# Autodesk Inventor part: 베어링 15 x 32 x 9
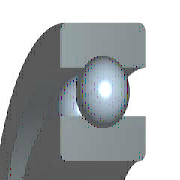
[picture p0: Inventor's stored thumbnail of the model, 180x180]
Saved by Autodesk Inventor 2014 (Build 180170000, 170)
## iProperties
IsCustomPart: 0
Created: 2012-02
Part Number: 베어링 15 x 32 x 9
Material: 강철, 연강
Description: 깊은 그루브 볼 베어링
Document SubType Name: Modeling
Standard: KS B 2023
Designer: mduedu
Standards Organization: KS
Language: ko-KR
Size Designation: 6002 - 15 x 32 x 9
Categories: <MemberInstance><Categories><Category DisplayName="샤프트 부품" InternalName="7f7aeb1f-a693-4053-b835-cee3144e0d98" Mnemonic="SHFT"><Category DisplayName="베어링" Inter
Density: 1 g/cm^3
Appearance: Yellow
Author: mduedu
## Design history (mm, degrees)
sketch "스케치" dims "d0" = 4.42 (= -0.26 x WD + 0.26 x BD)
  geometry: L1 (2.29, 11.75)-(6.71, 11.75); L2 (4.5, 11.75)-(4.5, 9.54); L3 (4.5, 11.75)-(4.5, 13.96); L4 (2.858, 10.271)-(0, 10.271); L5 (0, 7.5)-(9, 7.5); L6 (2.858, 13.229)-(0, 13.229); L7 (0, 16)-(9, 16); L8 (9, 7.5)-(9, 10.271); L9 (6.142, 10.271)-(9, 10.271); L10 (6.142, 13.229)-(9, 13.229); L11 (9, 16)-(9, 13.229); L12 (-1.4, 0)-(8.4, 0) reference; L13 (0, -0.3)-(0, 5.3) reference
  constraints: 22 end point, 4 point on line, 2 collinear, 2 perpendicular, 2 symmetric about line, 1 midpoint, 1 parallel, 14 other
  dimensions: "d9" = 15 diameter of L5 L12 (= WD); "d11" = 32 diameter of L7 L12 (= BD); "d12" = 9 distance between parallel lines of L8 L13 (= KB); "d13" = 20.542 diameter of L9 L12 (= 0.326 x BD + 0.674 x WD)
revolve "본체" stored, may be unused: angle "d6" = 90 deg
revolve "볼" stored, may be unused: angle "d7" = 90 deg
pattern_circular "IDS_ARRAYBALL[SIMPL:T]" dims angle "d3" = 360 deg
body "Solid1"
fillet "모깎기1" dims "d1" = 0.3 (= KRS)
other parameters: "WD" = 15 [user parameter; used in 5 equation terms], "BD" = 32 [user parameter; used in 5 equation terms], "KB" = 9 [user parameter; used in 1 equation term], "KRS" = 0.3 [user parameter; used in 1 equation term], "d4" = 0, "d5" = 0, "d8" = 0, "d14" = 0, "d15" = 0, "BBA" = 0 [user parameter], "BC0" = 2850000 [user parameter], "BC" = 5590000 [user parameter], "BR" = 16 (= 0.5 x BD) [user parameter], "WR" = 7.5 (= 0.5 x WD) [user parameter]
